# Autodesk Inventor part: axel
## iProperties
Author: Vincent Molino
Shininess: 20.0
Angle Display Precision: 2
Document Length Units: 11272
Document Angle Units: 11286
Document Time Units: 11279
Document Mass Units: 11290
Document Length Units Precision: 3
Document Angle Units Precision: 2
Compacted: True
PropertySet Name: _Private Model Information
Created: 2002-01
Part Number: axel
Document SubType Name: Modeling
Designer: Vincent Molino
Control State: 0
Master: False
Checked Out: False
PropertySet Name: Design Tracking Control
Density: 0.0
Volumn: 0.0
Area: 0.0
PropertySet Name: Model Information
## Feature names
1. Extrusion1
